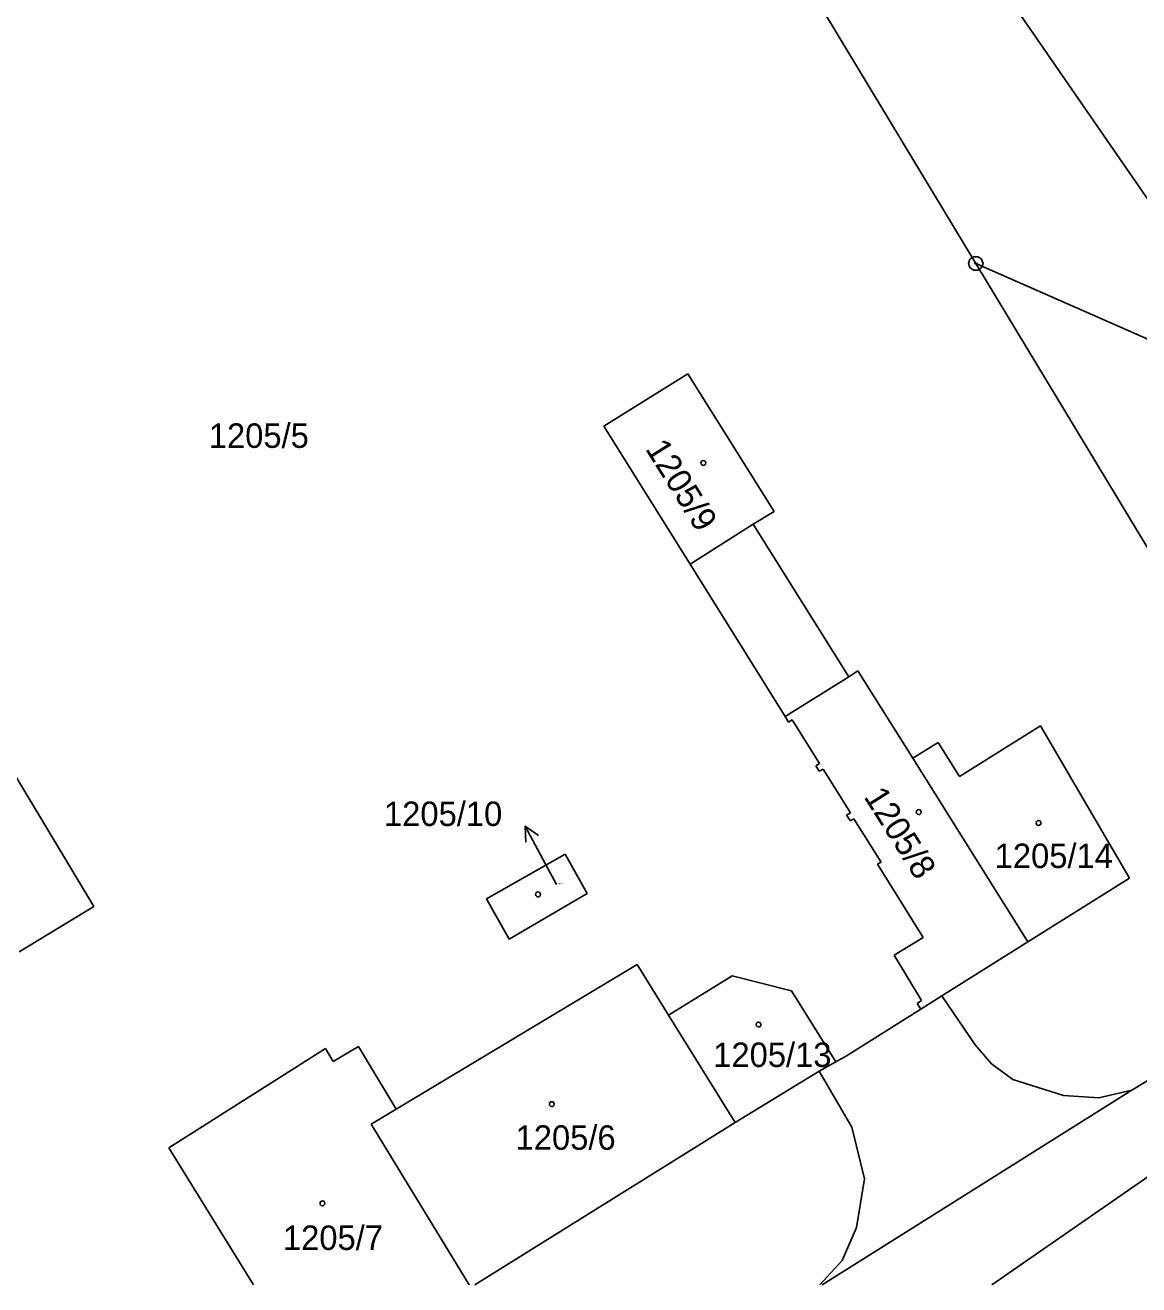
# Model space of a CAD drawing. Extents: x -777309 to -774195, y -1144706 to -1143600.
# Drawn here: x -775484.3 to -775406.9, y -1144700 to -1144612.5 of the extents above; entities that cross this region are included whole.
import ezdxf

# ---------------------------------------------------------------- set-up
doc = ezdxf.new("R2010")
doc.units = 0
for name, color, linetype in [('1', 7, 'Continuous'), ('11', 7, 'Continuous'), ('12', 7, 'Continuous'), ('2', 7, 'Continuous'), ('4', 7, 'Continuous'), ('5', 7, 'Continuous'), ('7', 7, 'Continuous'), ('8', 7, 'Continuous')]:
    doc.layers.add(name, color=color, linetype=linetype)

msp = doc.modelspace()

# ---------------------------------------------------------------- linework, layer by layer
at = {"layer": '1'}
for p, q in [((-775401.66, -1144631.36), (-775446.18, -1144566.73)), ((-775432.46, -1144605.51), (-775418.26, -1144629.06)), ((-775418.26, -1144629.06), (-775404.79, -1144651.38)), ((-775418.26, -1144629.06), (-775388.11, -1144642.34)), ((-775444.11, -1144640.36), (-775438.26, -1144636.71)), ((-775438.26, -1144636.71), (-775432.28, -1144646.27)), ((-775438.1, -1144649.94), (-775444.11, -1144640.36)), ((-775432.28, -1144646.27), (-775433.72, -1144647.17)), ((-775433.72, -1144647.17), (-775438.1, -1144649.94)), ((-775427.08, -1144657.76), (-775433.72, -1144647.17)), ((-775438.1, -1144649.94), (-775431.52, -1144660.52)), ((-775426.45, -1144657.36), (-775427.08, -1144657.76)), ((-775426.45, -1144657.36), (-775422.65, -1144663.42)), ((-775488.18, -1144659.34), (-775479.53, -1144673.73)), ((-775431.52, -1144660.52), (-775431.28, -1144660.91)), ((-775431.28, -1144660.91), (-775431.02, -1144660.75)), ((-775431.02, -1144660.75), (-775429.13, -1144663.79)), ((-775413.78, -1144661.18), (-775419.41, -1144664.7)), ((-775407.59, -1144671.75), (-775413.78, -1144661.18)), ((-775420.89, -1144662.32), (-775422.65, -1144663.42)), ((-775419.41, -1144664.7), (-775420.89, -1144662.32)), ((-775429.13, -1144663.79), (-775429.38, -1144663.94)), ((-775422.65, -1144663.42), (-775414.66, -1144676.18)), ((-775429.38, -1144663.94), (-775429.14, -1144664.33)), ((-775429.14, -1144664.33), (-775428.88, -1144664.18)), ((-775428.88, -1144664.18), (-775426.98, -1144667.21)), ((-775426.98, -1144667.21), (-775427.24, -1144667.37)), ((-775427.24, -1144667.37), (-775426.98, -1144667.78)), ((-775426.98, -1144667.78), (-775426.73, -1144667.62)), ((-775426.73, -1144667.62), (-775424.84, -1144670.63)), ((-775452.25, -1144673.18), (-775446.79, -1144670.09)), ((-775446.79, -1144670.09), (-775445.26, -1144672.81)), ((-775424.84, -1144670.63), (-775425.1, -1144670.79)), ((-775425.1, -1144670.79), (-775421.92, -1144675.88)), ((-775414.66, -1144676.18), (-775407.59, -1144671.75)), ((-775450.68, -1144675.98), (-775452.25, -1144673.18)), ((-775445.26, -1144672.81), (-775450.68, -1144675.98)), ((-775479.53, -1144673.73), (-775484.72, -1144676.87)), ((-775421.92, -1144675.88), (-775423.94, -1144677.11)), ((-775407.43, -1144686.48), (-775390, -1144675.91)), ((-775420.62, -1144679.93), (-775414.66, -1144676.18)), ((-775441.8, -1144677.75), (-775458.54, -1144687.79)), ((-775439.61, -1144681.28), (-775441.8, -1144677.75)), ((-775423.94, -1144677.11), (-775422.03, -1144680.26)), ((-775435.18, -1144678.53), (-775439.61, -1144681.28)), ((-775431.07, -1144679.59), (-775435.18, -1144678.53)), ((-775428, -1144684.52), (-775431.07, -1144679.59)), ((-775422.03, -1144680.26), (-775422.33, -1144680.45)), ((-775420.62, -1144679.93), (-775422.08, -1144680.85)), ((-775434.98, -1144688.73), (-775439.61, -1144681.28)), ((-775422.33, -1144680.45), (-775422.08, -1144680.85)), ((-775463.44, -1144683.59), (-775474.32, -1144690.48)), ((-775462.9, -1144684.49), (-775463.44, -1144683.59)), ((-775462.9, -1144684.49), (-775461.15, -1144683.44)), ((-775461.15, -1144683.44), (-775458.54, -1144687.79)), ((-775429.15, -1144685.15), (-775428, -1144684.52)), ((-775429.15, -1144685.15), (-775434.98, -1144688.73)), ((-775407.43, -1144686.48), (-775428.932, -1144700)), ((-775458.54, -1144687.79), (-775460.27, -1144688.83)), ((-775460.27, -1144688.83), (-775453.46, -1144700)), ((-775453.061, -1144700), (-775434.98, -1144688.73)), ((-775468.441, -1144700), (-775474.32, -1144690.48))]:
    msp.add_line(p, q, dxfattribs=at)
at = {"layer": '11'}
msp.add_lwpolyline([(-775428.932, -1144700), (-775407.43, -1144686.48), (-775390, -1144675.91), (-775354.18, -1144649.53), (-775318.59, -1144623.31), (-775317.85, -1144622.66), (-775257.86, -1144578.79), (-775246.07, -1144570.05), (-775235.05, -1144561.78), (-775230.93, -1144558.83), (-775228.56, -1144557.06), (-775225.17, -1144558.7), (-775210.47, -1144547.88), (-775189.95, -1144532.5), (-775159.15, -1144509.7)], dxfattribs=at)
at = {"layer": '12'}
for p, q in [((-775401.66, -1144631.36), (-775446.18, -1144566.73)), ((-775444.11, -1144640.36), (-775438.26, -1144636.71)), ((-775438.26, -1144636.71), (-775432.28, -1144646.27)), ((-775438.1, -1144649.94), (-775444.11, -1144640.36)), ((-775432.28, -1144646.27), (-775433.72, -1144647.17)), ((-775433.72, -1144647.17), (-775438.1, -1144649.94)), ((-775426.45, -1144657.36), (-775427.08, -1144657.76)), ((-775426.45, -1144657.36), (-775422.65, -1144663.42)), ((-775431.52, -1144660.52), (-775427.08, -1144657.76)), ((-775431.52, -1144660.52), (-775431.28, -1144660.91)), ((-775431.28, -1144660.91), (-775431.02, -1144660.75)), ((-775431.02, -1144660.75), (-775429.13, -1144663.79)), ((-775413.78, -1144661.18), (-775419.41, -1144664.7)), ((-775407.59, -1144671.75), (-775413.78, -1144661.18)), ((-775420.89, -1144662.32), (-775422.65, -1144663.42)), ((-775419.41, -1144664.7), (-775420.89, -1144662.32)), ((-775429.13, -1144663.79), (-775429.38, -1144663.94)), ((-775422.65, -1144663.42), (-775414.66, -1144676.18)), ((-775422.65, -1144663.42), (-775414.66, -1144676.18)), ((-775429.38, -1144663.94), (-775429.14, -1144664.33)), ((-775429.14, -1144664.33), (-775428.88, -1144664.18)), ((-775428.88, -1144664.18), (-775426.98, -1144667.21)), ((-775426.98, -1144667.21), (-775427.24, -1144667.37)), ((-775427.24, -1144667.37), (-775426.98, -1144667.78)), ((-775426.98, -1144667.78), (-775426.73, -1144667.62)), ((-775426.73, -1144667.62), (-775424.84, -1144670.63)), ((-775452.25, -1144673.18), (-775446.79, -1144670.09)), ((-775446.79, -1144670.09), (-775445.26, -1144672.81)), ((-775424.84, -1144670.63), (-775425.1, -1144670.79)), ((-775425.1, -1144670.79), (-775421.92, -1144675.88)), ((-775414.66, -1144676.18), (-775407.59, -1144671.75)), ((-775450.68, -1144675.98), (-775452.25, -1144673.18)), ((-775445.26, -1144672.81), (-775450.68, -1144675.98)), ((-775421.92, -1144675.88), (-775423.94, -1144677.11)), ((-775420.62, -1144679.93), (-775414.66, -1144676.18)), ((-775441.8, -1144677.75), (-775458.54, -1144687.79)), ((-775439.61, -1144681.28), (-775441.8, -1144677.75)), ((-775423.94, -1144677.11), (-775422.03, -1144680.26)), ((-775435.18, -1144678.53), (-775439.61, -1144681.28)), ((-775431.07, -1144679.59), (-775435.18, -1144678.53)), ((-775428, -1144684.52), (-775431.07, -1144679.59)), ((-775422.03, -1144680.26), (-775422.33, -1144680.45)), ((-775420.62, -1144679.93), (-775422.08, -1144680.85)), ((-775434.98, -1144688.73), (-775439.61, -1144681.28)), ((-775434.98, -1144688.73), (-775439.61, -1144681.28)), ((-775422.33, -1144680.45), (-775422.08, -1144680.85)), ((-775463.44, -1144683.59), (-775474.32, -1144690.48)), ((-775462.9, -1144684.49), (-775463.44, -1144683.59)), ((-775462.9, -1144684.49), (-775461.15, -1144683.44)), ((-775461.15, -1144683.44), (-775458.54, -1144687.79)), ((-775429.15, -1144685.15), (-775428, -1144684.52)), ((-775429.15, -1144685.15), (-775434.98, -1144688.73)), ((-775458.54, -1144687.79), (-775460.27, -1144688.83)), ((-775458.54, -1144687.79), (-775460.27, -1144688.83)), ((-775460.27, -1144688.83), (-775453.46, -1144700)), ((-775460.27, -1144688.83), (-775453.46, -1144700)), ((-775453.061, -1144700), (-775434.98, -1144688.73)), ((-775468.441, -1144700), (-775474.32, -1144690.48))]:
    msp.add_line(p, q, dxfattribs=at)
at = {"layer": '4'}
for p, q in [((-775431.52, -1144660.52), (-775427.08, -1144657.76)), ((-775418.31, -1144683.33), (-775420.62, -1144679.93)), ((-775427.32, -1144684.14), (-775422.08, -1144680.85)), ((-775417.18, -1144684.65), (-775418.31, -1144683.33)), ((-775428, -1144684.52), (-775427.32, -1144684.14)), ((-775415.69, -1144685.73), (-775417.18, -1144684.65)), ((-775426.88, -1144689.04), (-775429.15, -1144685.15)), ((-775412.17, -1144686.84), (-775415.69, -1144685.73)), ((-775407.43, -1144686.48), (-775409.72, -1144687.01)), ((-775409.72, -1144687.01), (-775412.17, -1144686.84)), ((-775426, -1144692.64), (-775426.88, -1144689.04)), ((-775417.147, -1144700), (-775404.05, -1144690.93)), ((-775426.55, -1144696.02), (-775426, -1144692.64)), ((-775427.55, -1144698.3), (-775426.55, -1144696.02)), ((-775429.102, -1144700), (-775427.55, -1144698.3))]:
    msp.add_line(p, q, dxfattribs=at)
at = {"layer": '5'}
for points in [[(-775437.2, -1144642.74), (-775437.1, -1144642.76), (-775437.05, -1144642.85), (-775437.03, -1144642.91), (-775437.05, -1144643), (-775437.13, -1144643.07), (-775437.2, -1144643.08), (-775437.29, -1144643.05), (-775437.35, -1144642.99), (-775437.37, -1144642.91), (-775437.35, -1144642.82), (-775437.27, -1144642.75)], [(-775422.23, -1144666.99), (-775422.13, -1144667.01), (-775422.08, -1144667.1), (-775422.06, -1144667.16), (-775422.08, -1144667.25), (-775422.16, -1144667.32), (-775422.23, -1144667.33), (-775422.32, -1144667.3), (-775422.38, -1144667.24), (-775422.4, -1144667.16), (-775422.38, -1144667.07), (-775422.3, -1144667)], [(-775413.91, -1144667.75), (-775413.81, -1144667.77), (-775413.76, -1144667.86), (-775413.74, -1144667.92), (-775413.76, -1144668.01), (-775413.84, -1144668.08), (-775413.91, -1144668.09), (-775414, -1144668.06), (-775414.06, -1144668), (-775414.08, -1144667.92), (-775414.06, -1144667.83), (-775413.98, -1144667.76)], [(-775448.68, -1144672.71), (-775448.58, -1144672.73), (-775448.53, -1144672.82), (-775448.51, -1144672.88), (-775448.53, -1144672.97), (-775448.61, -1144673.04), (-775448.68, -1144673.05), (-775448.77, -1144673.02), (-775448.83, -1144672.96), (-775448.85, -1144672.88), (-775448.83, -1144672.79), (-775448.75, -1144672.72)], [(-775433.36, -1144681.75), (-775433.26, -1144681.77), (-775433.21, -1144681.86), (-775433.19, -1144681.92), (-775433.21, -1144682.01), (-775433.29, -1144682.08), (-775433.36, -1144682.09), (-775433.45, -1144682.06), (-775433.51, -1144682), (-775433.53, -1144681.92), (-775433.51, -1144681.83), (-775433.43, -1144681.76)], [(-775447.72, -1144687.28), (-775447.62, -1144687.3), (-775447.57, -1144687.39), (-775447.55, -1144687.45), (-775447.57, -1144687.54), (-775447.65, -1144687.61), (-775447.72, -1144687.62), (-775447.81, -1144687.59), (-775447.87, -1144687.53), (-775447.89, -1144687.45), (-775447.87, -1144687.36), (-775447.79, -1144687.29)], [(-775463.65, -1144694.17), (-775463.55, -1144694.19), (-775463.5, -1144694.28), (-775463.48, -1144694.34), (-775463.5, -1144694.43), (-775463.58, -1144694.5), (-775463.65, -1144694.51), (-775463.74, -1144694.48), (-775463.8, -1144694.42), (-775463.82, -1144694.34), (-775463.8, -1144694.25), (-775463.72, -1144694.18)]]:
    msp.add_lwpolyline(points, close=True, dxfattribs=at)
at = {"layer": '7'}
for p in [(-775449.559, -1144668.132), (-775447.4, -1144672.19)]:
    msp.add_line(p, (-775448.15, -1144670.78), dxfattribs=at)
msp.add_lwpolyline([(-775449.531, -1144669.249), (-775449.559, -1144668.132), (-775448.648, -1144668.78)], dxfattribs=at)
at = {"layer": '8'}
msp.add_line((-775418.38, -1144629.06), (-775418.14, -1144629.06), dxfattribs=at)
msp.add_lwpolyline([(-775418.11, -1144628.58), (-775417.86, -1144628.76), (-775417.76, -1144629.05), (-775417.86, -1144629.34), (-775418.11, -1144629.52), (-775418.42, -1144629.52), (-775418.67, -1144629.34), (-775418.77, -1144629.05), (-775418.67, -1144628.76), (-775418.42, -1144628.58)], close=True, dxfattribs=at)

# ---------------------------------------------------------------- texts
at = {"layer": '2'}
for s, height, p in [('1205/5', 1.7, (-775471.547, -1144641.86)), ('1205/14', 1.7, (-775416.957, -1144671.05)), ('1205/10', 0.1, (-775447.377, -1144672.19)), ('1205/13', 1.7, (-775436.507, -1144684.87)), ('1205/6', 1.7, (-775450.237, -1144690.62)), ('1205/7', 1.7, (-775466.397, -1144697.58))]:
    msp.add_text(s, height=height, dxfattribs=at).set_placement(p)
for s, rotation, p in [('1205/9', 302.06335, (-775441.262, -1144641.923)), ('1205/8', 302.34983, (-775426.09, -1144666.092))]:
    msp.add_text(s, height=1.7, rotation=rotation, dxfattribs=at).set_placement(p)
at = {"layer": '7'}
msp.add_text('1205/10', height=1.7, dxfattribs=at).set_placement((-775459.377, -1144668.13))

doc.saveas('drawing.dxf')
